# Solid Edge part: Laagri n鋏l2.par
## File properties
Author: Türk
Template: Iso Part.par
Last saved by: Türk
Revision: 8
Application: Solid Edge
Accuracy: 0,990
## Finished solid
Body 1: solid body, 3 faces, 2 edges, 0 vertices.
  Faces by surface: plane 2, cylinder 1
  Edges by curve: circle 2
Bounding box of the edges (mm): 7.500 x 40.000 x 7.500, from (-3.75, 0, -3.75) to (3.75, 40, 3.75).
Cylindrical faces by radius (mm): R3.75 x1
Planar faces by outward normal: +y 1, -y 1
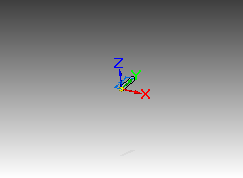
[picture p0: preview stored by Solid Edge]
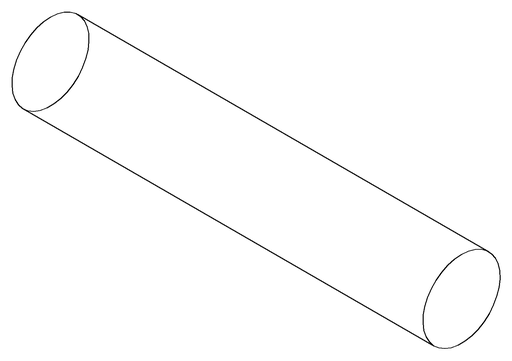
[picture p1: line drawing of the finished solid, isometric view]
